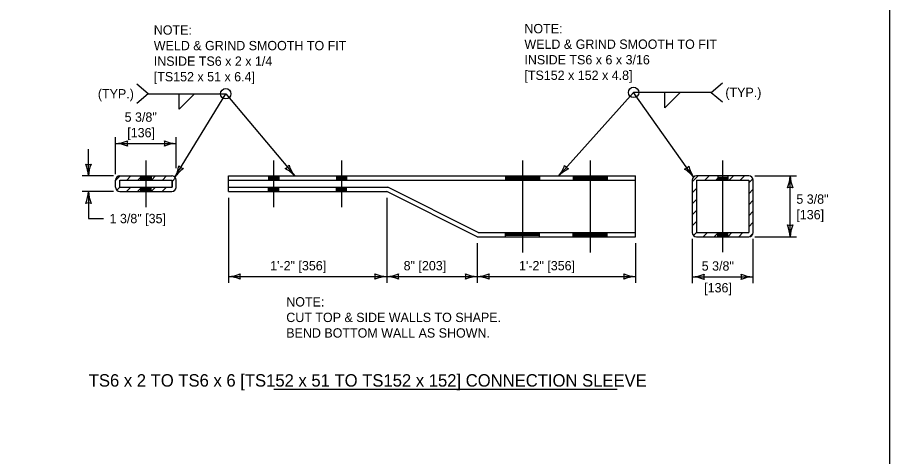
# Model space of a CAD drawing. Extents: x 49991.4 to 50021, y 49987.6 to 50011.4.
# Drawn here: x 50011.14 to 50016.75, y 49990.62 to 49993.45 of the extents above; entities that cross this region are included whole.
import ezdxf

# ---------------------------------------------------------------- set-up
doc = ezdxf.new("R2010")
doc.units = 0
for name, color, linetype in [('Level 1', 7, 'Continuous'), ('Level 2', 7, 'Continuous'), ('Level 3', 7, 'Continuous'), ('Level 4', 7, 'Continuous'), ('Level 5', 7, 'Continuous')]:
    doc.layers.add(name, color=color, linetype=linetype)

msp = doc.modelspace()

# ---------------------------------------------------------------- linework, layer by layer
at = {"layer": 'Level 1'}
for p, q in [((50011.7684, 49992.3978), (50011.7979, 49992.4273)), ((50011.7684, 49992.3545), (50011.7684, 49992.4002)), ((50011.7957, 49992.4273), (50012.1323, 49992.4273)), ((50011.7963, 49992.4002), (50012.1327, 49992.4002)), ((50011.7963, 49992.355), (50011.7963, 49992.4002)), ((50011.8415, 49992.4002), (50011.8686, 49992.4273)), ((50011.9122, 49992.4002), (50011.9327, 49992.4207)), ((50011.9969, 49992.4202), (50011.9327, 49992.4202)), ((50011.9969, 49992.4144), (50011.9327, 49992.4144)), ((50011.9969, 49992.4066), (50011.9327, 49992.4066)), ((50011.9999, 49992.4002), (50012.027, 49992.4273)), ((50012.0706, 49992.4002), (50012.0977, 49992.4273)), ((50012.1327, 49992.3916), (50012.1555, 49992.4144)), ((50012.1327, 49992.355), (50012.1327, 49992.4002)), ((50012.1327, 49992.4002), (50012.1327, 49992.355)), ((50012.1596, 49992.3545), (50012.1596, 49992.4002)), ((50012.4955, 49992.327), (50012.4955, 49992.4274)), ((50012.4955, 49992.4274), (50015.1159, 49992.4274)), ((50012.8189, 49992.4202), (50012.7543, 49992.4202)), ((50012.8189, 49992.4144), (50012.7543, 49992.4144)), ((50012.8189, 49992.4066), (50012.7543, 49992.4066)), ((50013.1911, 49992.4202), (50013.2545, 49992.4202)), ((50013.1911, 49992.4144), (50013.2545, 49992.4144)), ((50013.1911, 49992.4066), (50013.2545, 49992.4066)), ((50014.4965, 49992.4202), (50014.2779, 49992.4202)), ((50014.4965, 49992.4132), (50014.2779, 49992.4132)), ((50014.4965, 49992.406), (50014.2779, 49992.406)), ((50014.7147, 49992.4202), (50014.9333, 49992.4202)), ((50014.7147, 49992.4132), (50014.9333, 49992.4132)), ((50014.7147, 49992.406), (50014.9333, 49992.406)), ((50015.1159, 49992.036), (50015.1159, 49992.4274)), ((50015.4806, 49992.3905), (50015.5175, 49992.4275)), ((50015.4806, 49992.4002), (50015.4806, 49992.0638)), ((50015.8441, 49992.4275), (50015.5072, 49992.4275)), ((50015.5077, 49992.4002), (50015.8441, 49992.4002)), ((50015.5077, 49992.4002), (50015.5077, 49992.0638)), ((50015.561, 49992.4002), (50015.5882, 49992.4275)), ((50015.6317, 49992.4002), (50015.6443, 49992.4128)), ((50015.6443, 49992.4202), (50015.7083, 49992.4202)), ((50015.6443, 49992.4132), (50015.7083, 49992.4132)), ((50015.6443, 49992.406), (50015.7083, 49992.406)), ((50015.7189, 49992.4002), (50015.7461, 49992.4275)), ((50015.7896, 49992.4002), (50015.8168, 49992.4275)), ((50015.8441, 49992.384), (50015.8697, 49992.4096)), ((50015.8441, 49992.4002), (50015.8441, 49992.0638)), ((50015.8713, 49992.4002), (50015.8713, 49992.0638)), ((50011.7764, 49992.3351), (50011.7963, 49992.355)), ((50011.7963, 49992.355), (50012.1327, 49992.355)), ((50011.8392, 49992.3272), (50011.867, 49992.355)), ((50011.9099, 49992.3272), (50011.9327, 49992.35)), ((50011.9975, 49992.3478), (50011.9327, 49992.3478)), ((50011.9975, 49992.3406), (50011.9327, 49992.3406)), ((50011.9975, 49992.3336), (50011.9327, 49992.3336)), ((50011.9976, 49992.3272), (50012.0254, 49992.355)), ((50012.0683, 49992.3272), (50012.0961, 49992.355)), ((50012.1402, 49992.3284), (50012.1584, 49992.3466)), ((50012.8189, 49992.3478), (50012.7543, 49992.3478)), ((50012.8189, 49992.3406), (50012.7543, 49992.3406)), ((50012.8189, 49992.3336), (50012.7543, 49992.3336)), ((50013.1911, 49992.3478), (50013.2545, 49992.3478)), ((50013.1911, 49992.3406), (50013.2545, 49992.3406)), ((50013.1911, 49992.3336), (50013.2545, 49992.3336)), ((50015.4806, 49992.3198), (50015.5077, 49992.347)), ((50015.8441, 49992.3133), (50015.8713, 49992.3405)), ((50011.7957, 49992.3272), (50012.1323, 49992.3272)), ((50012.4955, 49992.327), (50013.5145, 49992.327)), ((50014.0967, 49992.036), (50013.5145, 49992.327)), ((50015.4806, 49992.2491), (50015.5077, 49992.2762)), ((50015.8441, 49992.2426), (50015.8713, 49992.2698)), ((50015.4806, 49992.1784), (50015.5077, 49992.2055)), ((50015.8441, 49992.1719), (50015.8713, 49992.1991)), ((50015.4806, 49992.1077), (50015.5077, 49992.1348)), ((50015.8441, 49992.1012), (50015.8713, 49992.1284)), ((50014.4965, 49992.0574), (50014.2779, 49992.0574)), ((50014.7147, 49992.0574), (50014.9333, 49992.0574)), ((50015.4884, 49992.0447), (50015.5077, 49992.0641)), ((50015.5077, 49992.0638), (50015.8441, 49992.0638)), ((50015.5509, 49992.0365), (50015.5781, 49992.0638)), ((50015.6216, 49992.0365), (50015.6443, 49992.0593)), ((50015.6443, 49992.0574), (50015.7083, 49992.0574)), ((50015.7088, 49992.0365), (50015.736, 49992.0638)), ((50015.7795, 49992.0365), (50015.8067, 49992.0638)), ((50015.8511, 49992.0375), (50015.8704, 49992.0568)), ((50014.0967, 49992.036), (50015.1159, 49992.036)), ((50014.4965, 49992.0502), (50014.2779, 49992.0502)), ((50014.4965, 49992.0438), (50014.2779, 49992.0438)), ((50014.7147, 49992.0502), (50014.9333, 49992.0502)), ((50014.7147, 49992.0438), (50014.9333, 49992.0438)), ((50015.5079, 49992.0365), (50015.8441, 49992.0365)), ((50015.6443, 49992.0502), (50015.7083, 49992.0502)), ((50015.6443, 49992.0438), (50015.7083, 49992.0438))]:
    msp.add_line(p, q, dxfattribs=at)
msp.add_lwpolyline([(49999.3835, 49998.9992), (50016.7501, 49998.9992), (50016.7501, 49987.7988), (49999.3835, 49987.7988)], close=True, dxfattribs=at)
for centre, start, end in [((50011.7957, 49992.4), 90, 180), ((50012.1323, 49992.4), 31.7885, 90), ((50012.1323, 49992.4), 0, 89.1858), ((50015.5079, 49992.4002), 91.4702, 180), ((50015.8441, 49992.4002), 0, 90), ((50011.7957, 49992.3545), 180, 270), ((50012.1323, 49992.3545), 270, 0), ((50012.1323, 49992.3545), 270, 0), ((50015.5079, 49992.0638), 180, 270), ((50015.8441, 49992.0638), 270, 0)]:
    msp.add_arc(centre, 0.0273, start, end, dxfattribs=at)
at = {"layer": 'Level 2'}
msp.add_line((50012.7883, 49991.0567), (50014.9967, 49991.0567), dxfattribs=at)
at = {"layer": 'Level 3'}
for p, q in [((50011.9787, 49992.956), (50011.9055, 49993.0174)), ((50015.6026, 49992.965), (50015.6758, 49993.0264)), ((50011.9787, 49992.956), (50011.9055, 49992.8946)), ((50011.9787, 49992.956), (50012.478, 49992.956)), ((50012.1516, 49992.4193), (50012.4781, 49992.956)), ((50012.1787, 49992.857), (50012.1787, 49992.956)), ((50012.1787, 49992.857), (50012.2781, 49992.956)), ((50012.4781, 49992.956), (50012.9222, 49992.4274)), ((50015.1029, 49992.965), (50014.6209, 49992.4274)), ((50015.6026, 49992.965), (50015.1027, 49992.9651)), ((50015.4888, 49992.4197), (50015.1028, 49992.9651)), ((50015.3029, 49992.8661), (50015.3029, 49992.9649)), ((50015.303, 49992.8661), (50015.4024, 49992.9649)), ((50015.6026, 49992.965), (50015.6758, 49992.9036)), ((50011.7689, 49992.44), (50011.7689, 49992.6762)), ((50012.1596, 49992.4774), (50012.1596, 49992.6762)), ((50011.7689, 49992.6362), (50012.1596, 49992.6362)), ((50011.5946, 49992.4274), (50011.5946, 49992.6008)), ((50011.7557, 49992.4274), (50011.5546, 49992.4274)), ((50015.8841, 49992.4275), (50016.1503, 49992.4275)), ((50016.1103, 49992.0365), (50016.1103, 49992.4275)), ((50011.7557, 49992.3271), (50011.5546, 49992.3271)), ((50011.5946, 49992.3271), (50011.5946, 49992.1536)), ((50012.4954, 49992.287), (50012.4954, 49991.7405)), ((50013.5144, 49992.287), (50013.5144, 49991.7405)), ((50011.5946, 49992.1536), (50011.6907, 49992.1536)), ((50014.0966, 49991.996), (50014.0966, 49991.7405)), ((50015.1157, 49991.996), (50015.1157, 49991.7405)), ((50015.4805, 49992.0238), (50015.4805, 49991.7386)), ((50015.8712, 49992.0238), (50015.8712, 49991.7386)), ((50015.8841, 49992.0365), (50016.1503, 49992.0365)), ((50012.4954, 49991.7805), (50013.5144, 49991.7805)), ((50013.5144, 49991.7805), (50014.0966, 49991.7805)), ((50014.0966, 49991.7805), (50015.1157, 49991.7805)), ((50015.4805, 49991.7786), (50015.8712, 49991.7786))]:
    msp.add_line(p, q, dxfattribs=at)
for centre in [(50012.4781, 49992.956), (50015.1028, 49992.9651)]:
    msp.add_circle(centre, 0.0335, dxfattribs=at)
for centre, radius, start, end in [((50011.7575, 49992.8689), 0.233, 272.8273, 292.0772), ((50011.7598, 49992.414), 0.2223, 67.456, 87.6395), ((50011.8972, 49992.6362), 0.0548, 162.1388, 197.8612), ((50012.1687, 49992.8583), 0.2223, 247.456, 267.6395), ((50012.0314, 49992.6362), 0.0548, 342.1388, 17.8612), ((50012.1711, 49992.4035), 0.233, 92.8273, 112.0772), ((50011.5946, 49992.5556), 0.0548, 252.1388, 287.8612), ((50011.3619, 49992.4159), 0.233, 2.8273, 22.0772), ((50011.8167, 49992.4183), 0.2223, 157.456, 177.6395), ((50011.9468, 49992.5304), 0.233, 331.5137, 350.7636), ((50012.3366, 49992.296), 0.2223, 126.1424, 146.3259), ((50012.2182, 49992.5288), 0.0548, 220.8252, 256.5476), ((50012.8397, 49992.5256), 0.0548, 292.1706, 327.893), ((50012.7514, 49992.2689), 0.233, 42.8591, 62.109), ((50013.0981, 49992.5633), 0.2223, 197.4878, 217.6713), ((50014.44, 49992.5742), 0.233, 320.9605, 340.2104), ((50014.7802, 49992.2723), 0.2223, 115.5892, 135.7727), ((50014.7065, 49992.5229), 0.0548, 210.272, 245.9944), ((50015.4147, 49992.5243), 0.0548, 287.422, 323.1444), ((50015.3054, 49992.2759), 0.233, 38.1105, 57.3604), ((50015.6754, 49992.5405), 0.2223, 192.7392, 212.9227), ((50015.8881, 49992.4366), 0.2223, 337.456, 357.6395), ((50016.343, 49992.439), 0.233, 182.8273, 202.0772), ((50016.1103, 49992.2993), 0.0548, 72.1388, 107.8612), ((50011.3724, 49992.3363), 0.2223, 337.456, 357.6395), ((50011.8273, 49992.3386), 0.233, 182.8273, 202.0772), ((50011.5946, 49992.1989), 0.0548, 72.1388, 107.8612), ((50016.1103, 49992.1648), 0.0548, 252.1388, 287.8612), ((50015.8776, 49992.025), 0.233, 2.8273, 22.0772), ((50016.3324, 49992.0274), 0.2223, 157.456, 177.6395), ((50012.484, 49992.0132), 0.233, 272.8273, 292.0772), ((50012.4863, 49991.5584), 0.2223, 67.456, 87.6395), ((50012.6237, 49991.7805), 0.0548, 162.1388, 197.8612), ((50013.5236, 49992.0027), 0.2223, 247.456, 267.6395), ((50013.3862, 49991.7805), 0.0548, 342.1388, 17.8612), ((50013.5259, 49991.5478), 0.233, 92.8273, 112.0772), ((50013.503, 49992.0132), 0.233, 272.8273, 292.0772), ((50013.5053, 49991.5584), 0.2223, 67.456, 87.6395), ((50013.6427, 49991.7805), 0.0548, 162.1388, 197.8612), ((50014.1058, 49992.0027), 0.2223, 247.456, 267.6395), ((50013.9684, 49991.7805), 0.0548, 342.1388, 17.8612), ((50014.1081, 49991.5478), 0.233, 92.8273, 112.0772), ((50014.0852, 49992.0132), 0.233, 272.8273, 292.0772), ((50014.0875, 49991.5584), 0.2223, 67.456, 87.6395), ((50014.2249, 49991.7805), 0.0548, 162.1388, 197.8612), ((50015.1249, 49992.0027), 0.2223, 247.456, 267.6395), ((50014.9875, 49991.7805), 0.0548, 342.1388, 17.8612), ((50015.1272, 49991.5478), 0.233, 92.8273, 112.0772), ((50015.4691, 49992.0114), 0.233, 272.8273, 292.0772), ((50015.4714, 49991.5565), 0.2223, 67.456, 87.6395), ((50015.6088, 49991.7786), 0.0548, 162.1388, 197.8612), ((50015.8804, 49992.0008), 0.2223, 247.456, 267.6395), ((50015.743, 49991.7786), 0.0548, 342.1388, 17.8612), ((50015.8827, 49991.5459), 0.233, 92.8273, 112.0772)]:
    msp.add_arc(centre, radius, start, end, dxfattribs=at)
at = {"layer": 'Level 4'}
for p, q in [((50011.9327, 49992.4273), (50011.9327, 49992.4002)), ((50011.9327, 49992.4002), (50011.9327, 49992.4273)), ((50011.9975, 49992.4273), (50011.9975, 49992.4002)), ((50012.4955, 49992.4002), (50015.1159, 49992.4002)), ((50012.7543, 49992.4274), (50012.7543, 49992.4002)), ((50012.8189, 49992.4274), (50012.8189, 49992.4002)), ((50013.1911, 49992.4274), (50013.1911, 49992.4002)), ((50013.2545, 49992.4274), (50013.2545, 49992.4002)), ((50014.2779, 49992.4274), (50014.2779, 49992.4002)), ((50014.4965, 49992.4274), (50014.4965, 49992.4002)), ((50014.7147, 49992.4274), (50014.7147, 49992.4002)), ((50014.9333, 49992.4274), (50014.9333, 49992.4002)), ((50015.6443, 49992.4275), (50015.6443, 49992.4002)), ((50015.7083, 49992.4275), (50015.7083, 49992.4002)), ((50011.9327, 49992.3272), (50011.9327, 49992.355)), ((50011.9327, 49992.3272), (50011.9327, 49992.355)), ((50011.9975, 49992.3272), (50011.9975, 49992.355)), ((50012.4955, 49992.355), (50013.5211, 49992.355)), ((50012.7543, 49992.327), (50012.7543, 49992.355)), ((50012.8189, 49992.327), (50012.8189, 49992.355)), ((50013.1911, 49992.327), (50013.1911, 49992.355)), ((50013.2545, 49992.327), (50013.2545, 49992.355)), ((50014.1033, 49992.0638), (50013.5211, 49992.355)), ((50014.1033, 49992.0638), (50015.1159, 49992.0638)), ((50014.2779, 49992.036), (50014.2779, 49992.0638)), ((50014.4965, 49992.036), (50014.4965, 49992.0638)), ((50014.7147, 49992.036), (50014.7147, 49992.0638)), ((50014.9333, 49992.036), (50014.9333, 49992.0638)), ((50015.6443, 49992.0365), (50015.6443, 49992.0638)), ((50015.7083, 49992.0365), (50015.7083, 49992.0638))]:
    msp.add_line(p, q, dxfattribs=at)
at = {"layer": 'Level 5'}
for p, q in [((50011.9643, 49992.5273), (50011.9643, 49992.2272)), ((50012.7866, 49992.5274), (50012.7866, 49992.227)), ((50013.2233, 49992.5274), (50013.2233, 49992.227)), ((50014.3878, 49992.5274), (50014.3878, 49991.936)), ((50014.8245, 49992.5274), (50014.8245, 49991.936)), ((50015.6758, 49992.5275), (50015.6758, 49991.9366))]:
    msp.add_line(p, q, dxfattribs=at)

# ---------------------------------------------------------------- texts
at = {"layer": 'Level 2'}
for s, height, p in [('NOTE:', 0.06, (50014.4003, 49993.3451)), ('NOTE:', 0.06, (50012.0153, 49993.336)), ('WELD & GRIND SMOOTH TO FIT', 0.06, (50012.0153, 49993.236)), ('WELD & GRIND SMOOTH TO FIT', 0.06, (50014.4003, 49993.2451)), ('INSIDE TS6 x 2 x 1/4', 0.06, (50012.0153, 49993.136)), ('INSIDE TS6 x 6 x 3/16', 0.06, (50014.4003, 49993.1451)), ('[TS152 x 51 x 6.4]', 0.06, (50012.0153, 49993.036)), ('[TS152 x 152 x 4.8]', 0.06, (50014.4003, 49993.0451)), ('(TYP.)', 0.06, (50011.6553, 49992.926)), ('(TYP.)', 0.06, (50015.6935, 49992.935)), ('5 3/8"', 0.06, (50011.8276, 49992.7762)), ('[136]', 0.06, (50011.8445, 49992.6762)), ('5 3/8"', 0.06, (50016.1503, 49992.2487)), ('1 3/8" [35]', 0.06, (50011.7307, 49992.1236)), ('[136]', 0.06, (50016.1503, 49992.1487)), ('1\'-2" [356]', 0.06, (50012.7643, 49991.8205)), ('8" [203]', 0.06, (50013.6231, 49991.8205)), ('1\'-2" [356]', 0.06, (50014.3656, 49991.8205)), ('5 3/8"', 0.06, (50015.5412, 49991.8186)), ('[136]', 0.06, (50015.5571, 49991.6786)), ('NOTE:  ', 0.06, (50012.8679, 49991.5879)), ('CUT TOP & SIDE WALLS TO SHAPE.', 0.06, (50012.8679, 49991.4879)), ('BEND BOTTOM WALL AS SHOWN.', 0.06, (50012.8679, 49991.3879)), ('TS6 x 2 TO TS6 x 6 [TS152 x 51 TO TS152 x 152] CONNECTION SLEEVE', 0.08, (50011.5967, 49991.0726))]:
    msp.add_text(s, height=height, dxfattribs=at).set_placement(p)

doc.saveas('drawing.dxf')
